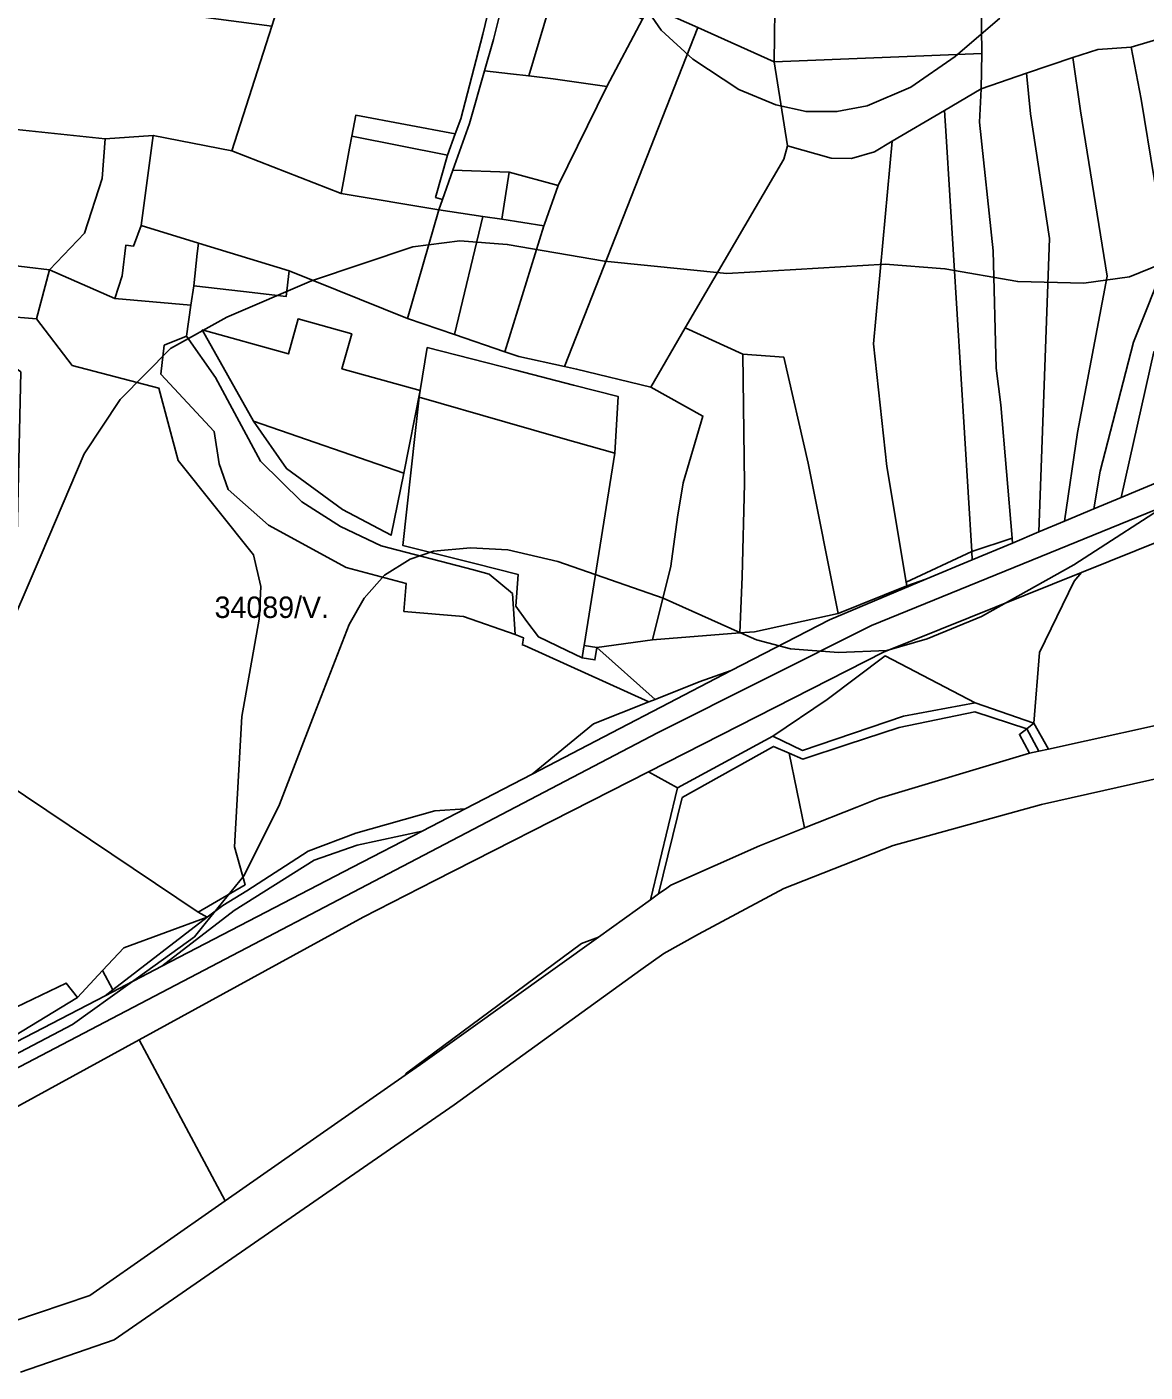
# Model space of a CAD drawing. Extents: x -535894 to -532834, y -1165802 to -1163645.
# Drawn here: x -534748.9 to -534487.4, y -1165553.6 to -1165239.2 of the extents above; entities that cross this region are included whole.
import ezdxf

# ---------------------------------------------------------------- set-up
doc = ezdxf.new("R2010")
doc.units = 0
for name, color, linetype in [('95560013', 7, 'Continuous'), ('95590013', 7, 'Continuous'), ('95600013', 7, 'Continuous'), ('95610013', 7, 'Continuous'), ('95630013', 7, 'Continuous'), ('95640013', 7, 'Continuous'), ('95660013', 7, 'Continuous')]:
    doc.layers.add(name, color=color, linetype=linetype)

msp = doc.modelspace()

# ---------------------------------------------------------------- linework, layer by layer
at = {"layer": '95560013'}
for points in [[(-534555.22, -1165133.48), (-534548.1, -1165130.49), (-534547.14, -1165136.27), (-534545.65, -1165145.14), (-534548.9, -1165148.28), (-534548.58, -1165157.34), (-534544.12, -1165157.18), (-534544.07, -1165158.63), (-534527.28, -1165157.93), (-534526.56, -1165167.24), (-534525.52, -1165245.33), (-534574.14, -1165247.28), (-534573.16, -1165174.91), (-534572.34, -1165142)], [(-534619.86, -1165211.52), (-534631.5, -1165250.59), (-534635.8, -1165250.1), (-534641.82, -1165249.4), (-534639.72, -1165242.1), (-534636.98, -1165231.14), (-534634.63, -1165222.23), (-534633.92, -1165220.53), (-534632.69, -1165217.6), (-534629.15, -1165214.48), (-534623.99, -1165212.98)], [(-534612.98, -1165209.1), (-534613.84, -1165233.07), (-534604.9, -1165237.35), (-534613.26, -1165253.08), (-534625.77, -1165251.25), (-534631.5, -1165250.59), (-534619.86, -1165211.52), (-534615.03, -1165209.82)], [(-534716.73, -1165313.55), (-534711.54, -1165311.45), (-534704.74, -1165321.13), (-534694.26, -1165340.63), (-534684.54, -1165350.12), (-534675.52, -1165355.92), (-534666.02, -1165360.45), (-534644.41, -1165366.09), (-534640.72, -1165367.06), (-534635.28, -1165371.61), (-534634.64, -1165381.14), (-534646.72, -1165376.99), (-534660.67, -1165375.77), (-534660.18, -1165369.23), (-534674.21, -1165365.47), (-534692.33, -1165355.62), (-534701.79, -1165347.3), (-534703.86, -1165341.25), (-534705.05, -1165333.73), (-534717.56, -1165320.29)]]:
    msp.add_lwpolyline(points, close=True, dxfattribs=at)
at = {"layer": '95590013'}
for points in [[(-534587.22, -1165174.4), (-534584.13, -1165174.48), (-534573.16, -1165174.91), (-534574.14, -1165247.28), (-534591.99, -1165239.3), (-534597.25, -1165236.95)], [(-534761.05, -1165235.16), (-534721.27, -1165235.1), (-534691.61, -1165239), (-534700.96, -1165268.14), (-534719.29, -1165264.53), (-534730.57, -1165265.33), (-534763.18, -1165261.89)], [(-534603.26, -1165234.27), (-534597.25, -1165236.95), (-534591.99, -1165239.3), (-534623.17, -1165318.51), (-534633.83, -1165316.18), (-534637.1, -1165315.06), (-534627.97, -1165285.63), (-534627.83, -1165285.22), (-534624.62, -1165276.23), (-534613.26, -1165253.08), (-534604.9, -1165237.35)], [(-534574.14, -1165247.28), (-534525.52, -1165245.33), (-534525.69, -1165253.61), (-534534.27, -1165258.67), (-534546.51, -1165265.89), (-534550.66, -1165268.35), (-534556, -1165269.92), (-534560.78, -1165269.82), (-534570.97, -1165266.95)], [(-534802.51, -1165263.09), (-534763.18, -1165261.89), (-534730.57, -1165265.33), (-534731.26, -1165274.58), (-534735.39, -1165287.4), (-534743.59, -1165295.91), (-534764.53, -1165293.41), (-534773.21, -1165290.92), (-534801.69, -1165282.74), (-534810.47, -1165278.22)], [(-534624.62, -1165276.23), (-534627.83, -1165285.22), (-534627.97, -1165285.63), (-534637.76, -1165284.12), (-534636.09, -1165273.14)], [(-534652.53, -1165281.94), (-534642.27, -1165283.46), (-534648.89, -1165311.07), (-534659.83, -1165307.34)], [(-534642.27, -1165283.46), (-534637.76, -1165284.12), (-534627.97, -1165285.63), (-534637.1, -1165315.06), (-534648.89, -1165311.07)], [(-534672.89, -1165310.88), (-534675.18, -1165319.07), (-534656.86, -1165324.17), (-534660.74, -1165343.46), (-534695.88, -1165331.28), (-534707.83, -1165309.96), (-534687.7, -1165315.57), (-534685.42, -1165307.39)], [(-534688.17, -1165342.38), (-534695.88, -1165331.28), (-534660.74, -1165343.46), (-534663.67, -1165357.97), (-534675.04, -1165351.98)]]:
    msp.add_lwpolyline(points, close=True, dxfattribs=at)
at = {"layer": '95600013'}
msp.add_lwpolyline([(-534526.42, -1165144.06), (-534506.66, -1165142.89), (-534505.88, -1165150.21), (-534486.55, -1165149.95), (-534482.37, -1165149.5), (-534479.49, -1165178.1), (-534474.69, -1165217.27), (-534470.72, -1165237.94), (-534490.64, -1165243.85), (-534498.4, -1165244.45), (-534504.24, -1165246.32), (-534515.07, -1165249.99), (-534525.69, -1165253.61), (-534525.52, -1165245.33), (-534526.56, -1165167.24), (-534526.49, -1165154.6)], close=True, dxfattribs=at)
at = {"layer": '95610013'}
for points in [[(-534635.35, -1165216.23), (-534636.93, -1165221.04), (-534639.56, -1165229.81), (-534642.21, -1165240.82), (-534647.4, -1165260.65), (-534648.68, -1165264.17), (-534671.96, -1165259.81), (-534672.89, -1165264.71), (-534673.41, -1165267.52), (-534674.85, -1165275.19), (-534675.39, -1165278.09), (-534700.96, -1165268.14), (-534691.61, -1165239), (-534688.84, -1165230.36), (-534686.31, -1165229.5), (-534683.94, -1165228.77), (-534634.06, -1165213.3)], [(-534591.99, -1165239.3), (-534574.14, -1165247.28), (-534570.97, -1165266.95), (-534571.87, -1165270.05), (-534594.9, -1165309.5), (-534602.97, -1165323.34), (-534620.31, -1165319.14), (-534623.17, -1165318.51)], [(-534470.72, -1165237.94), (-534472.13, -1165251.45), (-534468.11, -1165285.65), (-534468.02, -1165297.74), (-534474.75, -1165304.46), (-534485.35, -1165315.07), (-534492.99, -1165349.16), (-534499.33, -1165351.82), (-534497.87, -1165342.96), (-534490.1, -1165312.82), (-534482.19, -1165293.14), (-534488.32, -1165256.04), (-534490.64, -1165243.85)], [(-534504.24, -1165246.32), (-534502.48, -1165258.78), (-534496.27, -1165297.39), (-534503.19, -1165333.95), (-534506.18, -1165354.68), (-534512.19, -1165357.2), (-534509.72, -1165288.59), (-534514.18, -1165259.48), (-534515.07, -1165249.99)], [(-534490.64, -1165243.85), (-534488.32, -1165256.04), (-534482.19, -1165293.14), (-534490.1, -1165312.82), (-534497.87, -1165342.96), (-534499.33, -1165351.82), (-534506.18, -1165354.68), (-534503.19, -1165333.95), (-534496.27, -1165297.39), (-534502.48, -1165258.78), (-534504.24, -1165246.32), (-534498.4, -1165244.45)], [(-534515.07, -1165249.99), (-534514.18, -1165259.48), (-534509.72, -1165288.59), (-534512.19, -1165357.2), (-534518.38, -1165359.8), (-534518.48, -1165358.66), (-534521.1, -1165327.5), (-534522.16, -1165318.88), (-534522.93, -1165291.48), (-534526.11, -1165261.43), (-534525.69, -1165253.61)], [(-534525.69, -1165253.61), (-534526.11, -1165261.43), (-534522.93, -1165291.48), (-534522.16, -1165318.88), (-534521.1, -1165327.5), (-534518.48, -1165358.66), (-534527.9, -1165361.77), (-534533.9, -1165264.67), (-534534.27, -1165258.67)], [(-534533.9, -1165264.67), (-534527.9, -1165361.77), (-534543.25, -1165368.91), (-534547.76, -1165341.88), (-534550.89, -1165313.21), (-534546.51, -1165265.89), (-534534.27, -1165258.67)], [(-534719.29, -1165264.53), (-534700.96, -1165268.14), (-534675.39, -1165278.09), (-534652.53, -1165281.94), (-534659.83, -1165307.34), (-534687.53, -1165296.2), (-534708.76, -1165289.69), (-534722.11, -1165285.6)], [(-534546.51, -1165265.89), (-534550.89, -1165313.21), (-534547.76, -1165341.88), (-534543.25, -1165368.91), (-534543.11, -1165369.79), (-534559.18, -1165376.29), (-534566.14, -1165341.15), (-534571.85, -1165316.34), (-534581.4, -1165315.61), (-534594.9, -1165309.5), (-534571.87, -1165270.05), (-534570.97, -1165266.95), (-534560.78, -1165269.82), (-534556, -1165269.92), (-534550.66, -1165268.35)], [(-534764.53, -1165293.41), (-534754.18, -1165306.73), (-534746.57, -1165307.35), (-534738.25, -1165318.32), (-534717.97, -1165323.6), (-534713.44, -1165340.52), (-534695.84, -1165362.52), (-534694.17, -1165369.98), (-534694.4, -1165374.89), (-534694.53, -1165377.59), (-534698.61, -1165400.31), (-534700.33, -1165430.79), (-534697.82, -1165439.67), (-534708.8, -1165446.03), (-534774.44, -1165402.06), (-534773.37, -1165397.58), (-534762.44, -1165404.62), (-534756.01, -1165383.07), (-534751.34, -1165367.38), (-534751.2, -1165361.26), (-534750.26, -1165319.8), (-534758.59, -1165313.74), (-534764.1, -1165305.72)], [(-534743.59, -1165295.91), (-534746.57, -1165307.35), (-534754.18, -1165306.73), (-534764.53, -1165293.41)], [(-534743.59, -1165295.91), (-534728.29, -1165302.64), (-534710.5, -1165304.17), (-534711.54, -1165311.45), (-534716.73, -1165313.55), (-534717.56, -1165320.29), (-534705.05, -1165333.73), (-534703.86, -1165341.25), (-534701.79, -1165347.3), (-534692.33, -1165355.62), (-534674.21, -1165365.47), (-534660.18, -1165369.23), (-534660.67, -1165375.77), (-534646.72, -1165376.99), (-534634.64, -1165381.14), (-534632.69, -1165381.98), (-534632.99, -1165383.48), (-534633.02, -1165383.62), (-534632.47, -1165383.72), (-534603.43, -1165396.91), (-534616.38, -1165402.05), (-534630.7, -1165413.78), (-534646.35, -1165421.89), (-534653.45, -1165422.42), (-534671.92, -1165427.59), (-534683.04, -1165431.83), (-534697.42, -1165441.07), (-534703.07, -1165444.48), (-534706.72, -1165447.2), (-534708.8, -1165446.03), (-534697.82, -1165439.67), (-534700.33, -1165430.79), (-534698.61, -1165400.31), (-534694.53, -1165377.59), (-534694.4, -1165374.89), (-534694.17, -1165369.98), (-534695.84, -1165362.52), (-534713.44, -1165340.52), (-534717.97, -1165323.6), (-534738.25, -1165318.32), (-534746.57, -1165307.35)], [(-534660.74, -1165343.46), (-534656.86, -1165324.17), (-534657.11, -1165325.73), (-534660.93, -1165360.38), (-534644.09, -1165364.61), (-534633.99, -1165367.14), (-534634.54, -1165374.52), (-534631.93, -1165378.09), (-534629.25, -1165381.75), (-534622.61, -1165384.94), (-534619.01, -1165386.65), (-534616.04, -1165387.12), (-534615.57, -1165384.17), (-534601.97, -1165396.33), (-534603.43, -1165396.91), (-534632.47, -1165383.72), (-534633.02, -1165383.62), (-534632.99, -1165383.48), (-534632.69, -1165381.98), (-534634.64, -1165381.14), (-534635.28, -1165371.61), (-534640.72, -1165367.06), (-534644.41, -1165366.09), (-534666.02, -1165360.45), (-534675.52, -1165355.92), (-534684.54, -1165350.12), (-534694.26, -1165340.63), (-534704.74, -1165321.13), (-534711.54, -1165311.45), (-534710.5, -1165304.17), (-534709.85, -1165299.65), (-534698.22, -1165300.99), (-534688.22, -1165302.15), (-534687.53, -1165296.2), (-534659.83, -1165307.34), (-534648.89, -1165311.07), (-534637.1, -1165315.06), (-534633.83, -1165316.18), (-534623.17, -1165318.51), (-534620.31, -1165319.14), (-534602.97, -1165323.34), (-534590.76, -1165330.1), (-534595.37, -1165345.7), (-534596.74, -1165353.72), (-534598.25, -1165365.19), (-534602.56, -1165382.4), (-534615.57, -1165384.17), (-534618.54, -1165383.7), (-534611.39, -1165338.79), (-534610.55, -1165325.54), (-534621.05, -1165322.85), (-534634.51, -1165319.42), (-534655.24, -1165314.11), (-534656.86, -1165324.17), (-534675.18, -1165319.07), (-534672.89, -1165310.88), (-534685.42, -1165307.39), (-534687.7, -1165315.57), (-534707.83, -1165309.96), (-534695.88, -1165331.28), (-534688.17, -1165342.38), (-534675.04, -1165351.98), (-534663.67, -1165357.97)], [(-534581.4, -1165315.61), (-534581.07, -1165345.98), (-534581.57, -1165367.64), (-534582.11, -1165380.79), (-534602.56, -1165382.4), (-534598.25, -1165365.19), (-534596.74, -1165353.72), (-534595.37, -1165345.7), (-534590.76, -1165330.1), (-534602.97, -1165323.34), (-534594.9, -1165309.5)], [(-534655.24, -1165314.11), (-534634.51, -1165319.42), (-534621.05, -1165322.85), (-534610.55, -1165325.54), (-534611.39, -1165338.79), (-534623.5, -1165335.33), (-534637.06, -1165331.46), (-534657.11, -1165325.73), (-534656.86, -1165324.17)], [(-534571.85, -1165316.34), (-534566.14, -1165341.15), (-534559.18, -1165376.29), (-534578.69, -1165380.51), (-534582.11, -1165380.79), (-534581.57, -1165367.64), (-534581.07, -1165345.98), (-534581.4, -1165315.61)], [(-534485.35, -1165315.07), (-534473.17, -1165340.76), (-534473.97, -1165341.2), (-534492.99, -1165349.16)], [(-534637.06, -1165331.46), (-534623.5, -1165335.33), (-534611.39, -1165338.79), (-534618.54, -1165383.7), (-534618.67, -1165384.51), (-534619.01, -1165386.65), (-534622.61, -1165384.94), (-534629.25, -1165381.75), (-534631.93, -1165378.09), (-534634.54, -1165374.52), (-534633.99, -1165367.14), (-534644.09, -1165364.61), (-534660.93, -1165360.38), (-534657.11, -1165325.73)], [(-534364.65, -1165326.48), (-534360.45, -1165326.25), (-534347.57, -1165373.21), (-534350.42, -1165373.76), (-534406.37, -1165385.09), (-534509.97, -1165407.93), (-534513.35, -1165401.93), (-534512.04, -1165385.37), (-534503.99, -1165368.68), (-534502.24, -1165366.65), (-534419.17, -1165333.25)], [(-534518.48, -1165358.66), (-534518.38, -1165359.8), (-534527.77, -1165363.73), (-534527.9, -1165361.77)], [(-534527.77, -1165363.73), (-534538.63, -1165368.27), (-534543.11, -1165369.79), (-534543.25, -1165368.91), (-534527.9, -1165361.77)], [(-534543.11, -1165369.79), (-534538.63, -1165368.27), (-534561.19, -1165377.71), (-534584.14, -1165389.62), (-534591.66, -1165392.25), (-534601.97, -1165396.33), (-534615.57, -1165384.17), (-534602.56, -1165382.4), (-534582.11, -1165380.79), (-534578.69, -1165380.51), (-534559.18, -1165376.29)], [(-534502.24, -1165366.65), (-534503.99, -1165368.68), (-534512.04, -1165385.37), (-534513.35, -1165401.93), (-534527.13, -1165397.14), (-534548.14, -1165386.16), (-534561.68, -1165396.35), (-534574.43, -1165404.96), (-534596.68, -1165416.98), (-534603.53, -1165413.28), (-534548.51, -1165385.26)], [(-534615.57, -1165384.17), (-534616.04, -1165387.12), (-534619.01, -1165386.65), (-534618.67, -1165384.51), (-534618.54, -1165383.7)], [(-534561.68, -1165396.35), (-534548.14, -1165386.16), (-534527.13, -1165397.14), (-534543.84, -1165400.27), (-534567.46, -1165408.26), (-534574.43, -1165404.96)], [(-534591.66, -1165392.25), (-534584.14, -1165389.62), (-534600.64, -1165398.18), (-534610.23, -1165403.15), (-534630.7, -1165413.78), (-534616.38, -1165402.05), (-534603.43, -1165396.91), (-534601.97, -1165396.33)], [(-534527.13, -1165397.14), (-534513.35, -1165401.93), (-534515.05, -1165403.23), (-534527.22, -1165399.28), (-534544.87, -1165402.87), (-534557.01, -1165406.86), (-534567.43, -1165410.29), (-534570.57, -1165408.93), (-534574.28, -1165407.33), (-534595.62, -1165419.29), (-534601.13, -1165441.8), (-534603.02, -1165443.16), (-534596.68, -1165416.98), (-534574.43, -1165404.96), (-534567.46, -1165408.26), (-534543.84, -1165400.27)], [(-534777.14, -1165399.85), (-534774.44, -1165402.06), (-534708.8, -1165446.03), (-534706.72, -1165447.2), (-534726.22, -1165454.44), (-534731.16, -1165459.74), (-534737, -1165466.01), (-534739.65, -1165462.65), (-534768.94, -1165476.68), (-534769.67, -1165481.85), (-534779.55, -1165483.95), (-534797.58, -1165460.25), (-534800.02, -1165457.14), (-534797.86, -1165446.44), (-534791.04, -1165427.36), (-534790.14, -1165428.15), (-534783.92, -1165413.27)], [(-534544.87, -1165402.87), (-534527.22, -1165399.28), (-534515.05, -1165403.23), (-534516.77, -1165404.52), (-534514.4, -1165408.9), (-534549.73, -1165419.5), (-534554.75, -1165421.51), (-534567.01, -1165426.39), (-534570.57, -1165408.93), (-534567.43, -1165410.29), (-534557.01, -1165406.86)], [(-534515.05, -1165403.23), (-534512.18, -1165408.41), (-534514.4, -1165408.9), (-534516.77, -1165404.52)], [(-534513.35, -1165401.93), (-534509.97, -1165407.93), (-534512.18, -1165408.41), (-534515.05, -1165403.23)], [(-534574.28, -1165407.33), (-534570.57, -1165408.93), (-534567.01, -1165426.39), (-534577.5, -1165430.58), (-534598.29, -1165439.76), (-534599.24, -1165440.45), (-534601.13, -1165441.8), (-534595.62, -1165419.29)], [(-534596.68, -1165416.98), (-534603.02, -1165443.16), (-534615.22, -1165451.89), (-534619.17, -1165453.43), (-534660.1, -1165483.67), (-534660.38, -1165484.14), (-534702.49, -1165513.54), (-534722.56, -1165475.88), (-534670.22, -1165447.23), (-534653.44, -1165438.69), (-534612.41, -1165417.8), (-534603.53, -1165413.28)], [(-534653.45, -1165422.42), (-534646.35, -1165421.89), (-534656.41, -1165427.11), (-534671.6, -1165430.4), (-534681.64, -1165433.88), (-534700.4, -1165445.64), (-534717.3, -1165458.7), (-534730.58, -1165465.6), (-534728.78, -1165464.21), (-534706.72, -1165447.2), (-534703.07, -1165444.48), (-534697.42, -1165441.07), (-534683.04, -1165431.83), (-534671.92, -1165427.59)], [(-534671.6, -1165430.4), (-534656.41, -1165427.11), (-534672.71, -1165435.57), (-534717.3, -1165458.7), (-534700.4, -1165445.64), (-534681.64, -1165433.88)], [(-534726.22, -1165454.44), (-534706.72, -1165447.2), (-534728.78, -1165464.21), (-534731.16, -1165459.74)], [(-534619.17, -1165453.43), (-534615.22, -1165451.89), (-534656.83, -1165481.66), (-534660.38, -1165484.14), (-534660.1, -1165483.67)], [(-534728.78, -1165464.21), (-534730.58, -1165465.6), (-534770.13, -1165486.11), (-534737, -1165466.01), (-534731.16, -1165459.74)], [(-534739.65, -1165462.65), (-534737, -1165466.01), (-534770.13, -1165486.11), (-534775.01, -1165488.64), (-534779.55, -1165483.95), (-534769.67, -1165481.85), (-534768.94, -1165476.68)], [(-534787.1, -1165511.18), (-534722.56, -1165475.88), (-534702.49, -1165513.54), (-534734.15, -1165535.63), (-534752.11, -1165541.71), (-534767.34, -1165543.34), (-534781.05, -1165543.94), (-534792.57, -1165513.75)]]:
    msp.add_lwpolyline(points, close=True, dxfattribs=at)
at = {"layer": '95630013'}
for points in [[(-534752.11, -1165541.71), (-534734.15, -1165535.63), (-534702.49, -1165513.54), (-534660.38, -1165484.14), (-534656.83, -1165481.66), (-534615.22, -1165451.89), (-534603.02, -1165443.16), (-534601.13, -1165441.8), (-534599.24, -1165440.45), (-534598.29, -1165439.76), (-534577.5, -1165430.58), (-534567.01, -1165426.39), (-534554.75, -1165421.51), (-534549.73, -1165419.5), (-534514.4, -1165408.9), (-534512.18, -1165408.41), (-534509.97, -1165407.93), (-534406.37, -1165385.09)], [(-534404.04, -1165396.72), (-534511.63, -1165420.88), (-534546.3, -1165430.52), (-534571.82, -1165440.57), (-534591.82, -1165451.2), (-534599.87, -1165455.71), (-534605.28, -1165459.52), (-534648.91, -1165491.07), (-534728.46, -1165546.03), (-534750.37, -1165553.57)]]:
    msp.add_lwpolyline(points, dxfattribs=at)
at = {"layer": '95640013'}
for points in [[(-534636.98, -1165231.14), (-534639.72, -1165242.1), (-534641.82, -1165249.4), (-534645.35, -1165261.71), (-534646.15, -1165263.94), (-534649.26, -1165272.62), (-534651.68, -1165279.51), (-534653.27, -1165279.03), (-534650.5, -1165269.13), (-534648.68, -1165264.17), (-534647.4, -1165260.65), (-534642.21, -1165240.82), (-534639.56, -1165229.81)], [(-534422.4, -1165326.53), (-534551.38, -1165379.05), (-534601.41, -1165404.16), (-534772.12, -1165493.42)], [(-534772.12, -1165493.42), (-534601.41, -1165404.16), (-534551.38, -1165379.05), (-534422.4, -1165326.53)], [(-534419.17, -1165333.25), (-534502.24, -1165366.65), (-534548.51, -1165385.26), (-534603.53, -1165413.28), (-534612.41, -1165417.8), (-534653.44, -1165438.69), (-534670.22, -1165447.23), (-534722.56, -1165475.88), (-534787.1, -1165511.18)], [(-534770.13, -1165486.11), (-534730.58, -1165465.6), (-534717.3, -1165458.7), (-534672.71, -1165435.57), (-534656.41, -1165427.11), (-534646.35, -1165421.89), (-534630.7, -1165413.78), (-534610.23, -1165403.15), (-534600.64, -1165398.18), (-534584.14, -1165389.62), (-534561.19, -1165377.71), (-534538.63, -1165368.27), (-534527.77, -1165363.73), (-534518.38, -1165359.8), (-534512.19, -1165357.2), (-534506.18, -1165354.68), (-534499.33, -1165351.82), (-534492.99, -1165349.16), (-534473.97, -1165341.2)]]:
    msp.add_lwpolyline(points, dxfattribs=at)
for points in [[(-534635.8, -1165250.1), (-534631.5, -1165250.59), (-534625.77, -1165251.25), (-534613.26, -1165253.08), (-534624.62, -1165276.23), (-534636.09, -1165273.14), (-534649.26, -1165272.62), (-534646.15, -1165263.94), (-534645.35, -1165261.71), (-534641.82, -1165249.4)], [(-534648.68, -1165264.17), (-534650.5, -1165269.13), (-534672.89, -1165264.71), (-534671.96, -1165259.81)], [(-534730.57, -1165265.33), (-534719.29, -1165264.53), (-534722.11, -1165285.6), (-534723.91, -1165290.37), (-534725.71, -1165290.16), (-534726.54, -1165297.31), (-534728.29, -1165302.64), (-534743.59, -1165295.91), (-534735.39, -1165287.4), (-534731.26, -1165274.58)], [(-534672.89, -1165264.71), (-534650.5, -1165269.13), (-534653.27, -1165279.03), (-534651.68, -1165279.51), (-534652.53, -1165281.94), (-534675.39, -1165278.09), (-534674.85, -1165275.19), (-534673.41, -1165267.52)], [(-534636.09, -1165273.14), (-534637.76, -1165284.12), (-534642.27, -1165283.46), (-534652.53, -1165281.94), (-534651.68, -1165279.51), (-534649.26, -1165272.62)], [(-534708.76, -1165289.69), (-534709.03, -1165292.09), (-534709.85, -1165299.65), (-534710.5, -1165304.17), (-534728.29, -1165302.64), (-534726.54, -1165297.31), (-534725.71, -1165290.16), (-534723.91, -1165290.37), (-534722.11, -1165285.6)], [(-534709.03, -1165292.09), (-534708.76, -1165289.69), (-534687.53, -1165296.2), (-534688.22, -1165302.15), (-534698.22, -1165300.99), (-534709.85, -1165299.65)]]:
    msp.add_lwpolyline(points, close=True, dxfattribs=at)
at = {"layer": '95660013'}
for points in [[(-534604.74, -1165233.86), (-534600.52, -1165239.92), (-534593.11, -1165246.69), (-534582.36, -1165253.77), (-534573.68, -1165257.329), (-534566.647, -1165258.95), (-534559.429, -1165258.95), (-534552.34, -1165257.6), (-534542.15, -1165253.22), (-534531.79, -1165246.05), (-534521.36, -1165237.13)], [(-534521.36, -1165237.13), (-534531.79, -1165246.05), (-534542.15, -1165253.22), (-534552.34, -1165257.6), (-534559.429, -1165258.95), (-534566.647, -1165258.95), (-534573.68, -1165257.329), (-534582.36, -1165253.77), (-534593.11, -1165246.69), (-534600.52, -1165239.92), (-534604.74, -1165233.86)], [(-534481.048, -1165293.523), (-534491.02, -1165297.58), (-534501.69, -1165299.01), (-534517.14, -1165298.69), (-534534.18, -1165295.66), (-534548.12, -1165294.571), (-534569.06, -1165295.82), (-534585.15, -1165296.78), (-534613.82, -1165293.91), (-534636.538, -1165289.974), (-534647.59, -1165289.13), (-534658.58, -1165290.571), (-534682.31, -1165298.53), (-534702.06, -1165306.97), (-534715.28, -1165314.3), (-534727.07, -1165326.25), (-534735.426, -1165338.913), (-534745.54, -1165362.56), (-534754.94, -1165384.54)], [(-534754.94, -1165384.54), (-534745.54, -1165362.56), (-534735.426, -1165338.913), (-534727.07, -1165326.25), (-534715.28, -1165314.3), (-534702.06, -1165306.97), (-534682.31, -1165298.53), (-534658.58, -1165290.571), (-534647.59, -1165289.13), (-534636.538, -1165289.974), (-534613.82, -1165293.91), (-534585.15, -1165296.78), (-534569.06, -1165295.82), (-534548.12, -1165294.571), (-534534.18, -1165295.66), (-534517.14, -1165298.69), (-534501.69, -1165299.01), (-534491.02, -1165297.58), (-534481.048, -1165293.523)], [(-534479.15, -1165348.82), (-534504, -1165364.91), (-534525.66, -1165376.94), (-534538.32, -1165382.19), (-534547.777, -1165384.87), (-534559.03, -1165385.38), (-534570.26, -1165384.5), (-534578.22, -1165382.43), (-534581.969, -1165380.76), (-534600.041, -1165372.71), (-534624.73, -1165364.11), (-534636.414, -1165361.355), (-534645.121, -1165360.93), (-534653.8, -1165361.72), (-534659.187, -1165363.557), (-534665.247, -1165367.305), (-534669.97, -1165372.64), (-534673.527, -1165378.814), (-534681.67, -1165399.87), (-534689.813, -1165420.926), (-534698.075, -1165437.459), (-534707.127, -1165448.709), (-534709.661, -1165451.859), (-534724.68, -1165462.63), (-534738.22, -1165472.34), (-534758.29, -1165482.861)], [(-534758.29, -1165482.861), (-534738.22, -1165472.34), (-534724.68, -1165462.63), (-534709.661, -1165451.859), (-534707.127, -1165448.709), (-534698.075, -1165437.459), (-534689.813, -1165420.926), (-534681.67, -1165399.87), (-534673.527, -1165378.814), (-534669.97, -1165372.64), (-534665.247, -1165367.305), (-534659.187, -1165363.557), (-534653.8, -1165361.72), (-534645.121, -1165360.93), (-534636.414, -1165361.355), (-534624.73, -1165364.11), (-534600.041, -1165372.71), (-534581.969, -1165380.76), (-534578.22, -1165382.43), (-534570.26, -1165384.5), (-534559.03, -1165385.38), (-534547.777, -1165384.87), (-534538.32, -1165382.19), (-534525.66, -1165376.94), (-534504, -1165364.91), (-534479.15, -1165348.82)], [(-534404.04, -1165396.72), (-534511.63, -1165420.88), (-534546.3, -1165430.52), (-534571.82, -1165440.57), (-534591.82, -1165451.2), (-534599.87, -1165455.71), (-534605.28, -1165459.52), (-534648.91, -1165491.07), (-534728.46, -1165546.03), (-534750.37, -1165553.57)]]:
    msp.add_lwpolyline(points, dxfattribs=at)

# ---------------------------------------------------------------- texts
msp.add_text('34089/V.', height=5, rotation=0, dxfattribs=at).set_placement((-534704.965, -1165377.301))

doc.saveas('drawing.dxf')
